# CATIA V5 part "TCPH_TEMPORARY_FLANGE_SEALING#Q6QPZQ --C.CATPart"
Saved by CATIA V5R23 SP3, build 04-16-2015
Part number: TCPH_TEMPORARY_FLANGE_SEALING#Q6QPXR
Revision: --C
Nomenclature: _
Description: TCPH_TEMPORARY_FLANGE_SEALING
Property "AT": "PD"
Property "REP": "CM"
Property "External Part ID": "_"
Property "Description Modification": "CRYOSTAT Technical Specification - UID: Q4TFX2 - WP2406"
Property "PREF": "Y"
Property "LONG": "_"
Property "PBS 1": "24"
Property "PBS 2": "CR"
Property "PBS 3": "LC"
Property "DEPT": "_"
Property "DIVN": "_"
Property "GROUP": "_"
Property "UNIT": "_"
Property "PARTY": "_"
Property "RO": "---"
Property "RE": "SEKACHI"
Property "PRO": "---"
Property "Change Type": "Minor"
Property "Maturity Level": "CD"
Property "Export Number": "_"
Property "Description Documents": "Q4TFX2"
Property "BOM": "_"
Property "ID": "Q6QPXR"
Property "User In Enovia": "VAUQUEJ"
Property "Object Type": "_"
Property "CADENAS_ID": "_"
Property "Life Cycle Status": "Approved"
Bounding box of the stored display mesh (mm): x 16800 to 16808, y -1218 to 1218, z -6073.846 to -3186
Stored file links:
  C:\Users\pandeym\Desktop\__TCPH\TCPH_TEMPORARY_FLANGE_SEALING#Q6QPZQ --C.CATPart
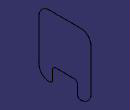
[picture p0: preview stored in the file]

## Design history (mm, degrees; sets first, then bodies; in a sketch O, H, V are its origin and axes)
Set1
  Sketch1 "TEMP_FLANGE_SEALING_GROOVE", origin (16800, 0, 0), H (0, 1, 0), V (0, 0, 1), geometry linked from another document
Body1 (main body)
  Sketch2 on zx-plane, origin (0, 0, 0), H (-1, 0, 0), V (0, 0, 1)
    circle A1 centre (-16804, -5363) radius 4
    point P1 (-16804, -5363)
    reference projected point E1 (-16800, -5363) from edge of Sketch1
    axis line L1 (-16804, -5363) -> (-16797.7774, -5363)
    reference projected point E2 (-16800, -5363) from edge of Sketch1
    radius A1 = 4
    distance E1 P1 = 4
    horizontal: L1 H
    coincidence: L1 E2
  Rib1: profile Sketch2, centre curve Sketch1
